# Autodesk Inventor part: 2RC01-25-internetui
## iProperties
Created: 2010-11
Part Number: 2RC01-25-internetui
Document SubType Name: Modeling
Designer: Darius
Author: Darius
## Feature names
1. Base1
